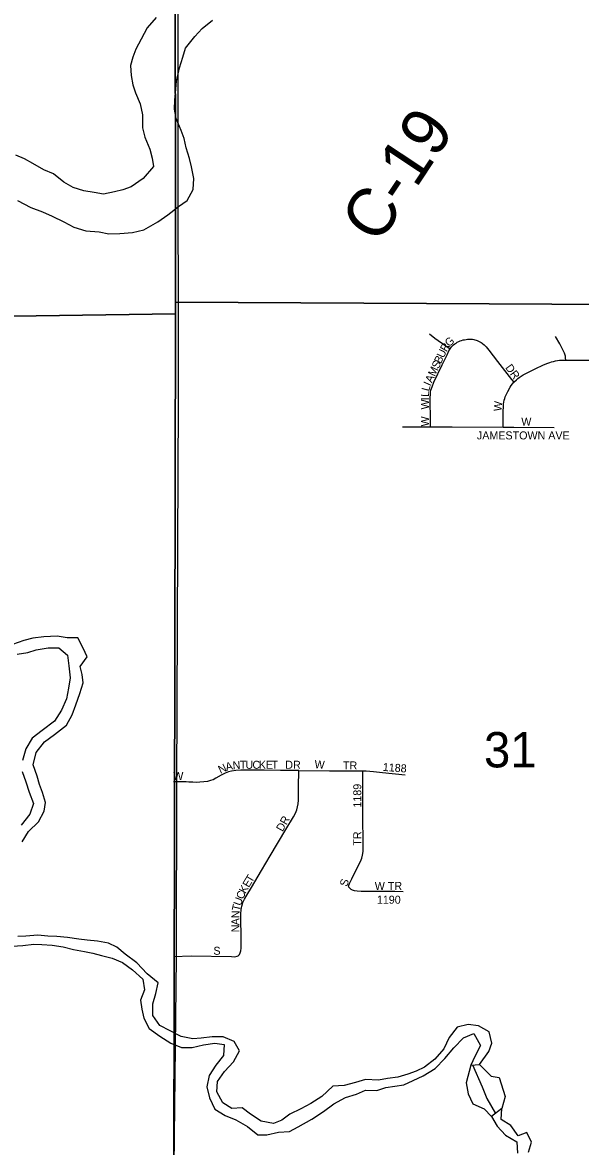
# Model space of a CAD drawing. Extents: x 1772825 to 1773716, y 1138558 to 1139032.
# Drawn here: x 1772827.893 to 1772828.223, y 1138561.147 to 1138561.812 of the extents above; entities that cross this region are included whole.
import ezdxf

# ---------------------------------------------------------------- set-up
doc = ezdxf.new("R2010")
doc.units = 0
for name, color, linetype in [('GM_X_County_Road_Text', 7, 'Continuous'), ('GM_X_Major_River', 7, 'Continuous'), ('GM_X_Minor_Lake', 7, 'Continuous'), ('GM_X_Minor_River', 7, 'Continuous'), ('GM_X_Section', 7, 'Continuous'), ('GM_X_Section_Text', 7, 'Continuous'), ('GM_X_Township', 7, 'Continuous'), ('GM_X_Township_Subdivision', 7, 'Continuous'), ('GM_X_Township_Subdivision_Text', 7, 'Continuous')]:
    doc.layers.add(name, color=color, linetype=linetype)

msp = doc.modelspace()

# ---------------------------------------------------------------- linework, layer by layer
at = {"layer": 'GM_X_Major_River'}
for points in [[(1772827.88993, 1138561.70647), (1772827.89787, 1138561.70243), (1772827.90468, 1138561.69972), (1772827.91055, 1138561.69721), (1772827.91735, 1138561.69393), (1772827.92321, 1138561.69066), (1772827.9304, 1138561.68852), (1772827.93818, 1138561.68789), (1772827.94405, 1138561.68671), (1772827.9505, 1138561.68704), (1772827.95791, 1138561.68755), (1772827.96475, 1138561.68921), (1772827.97294, 1138561.69389), (1772827.97885, 1138561.69802), (1772827.98515, 1138561.7029), (1772827.9903, 1138561.70647), (1772827.99395, 1138561.71308), (1772827.99419, 1138561.71953), (1772827.99291, 1138561.72637), (1772827.99162, 1138561.73131), (1772827.98977, 1138561.73759), (1772827.98848, 1138561.7431), (1772827.98681, 1138561.74786), (1772827.98382, 1138561.7549), (1772827.98291, 1138561.76041), (1772827.98295, 1138561.76591), (1772827.98357, 1138561.77236), (1772827.98398, 1138561.7771), (1772827.98575, 1138561.78487), (1772827.98769, 1138561.7913), (1772827.98925, 1138561.7966), (1772827.9948, 1138561.80339), (1772827.9992, 1138561.80829), (1772828.00531, 1138561.81318)], [(1772827.97192, 1138561.81476), (1772827.96657, 1138561.80854), (1772827.9631, 1138561.80193), (1772827.96002, 1138561.79607), (1772827.95809, 1138561.79115), (1772827.95673, 1138561.78623), (1772827.95725, 1138561.78034), (1772827.95816, 1138561.77483), (1772827.95984, 1138561.77007), (1772827.96245, 1138561.7636), (1772827.96392, 1138561.75714), (1772827.96386, 1138561.74936), (1772827.96534, 1138561.74385), (1772827.96832, 1138561.7368), (1772827.96961, 1138561.73148), (1772827.97033, 1138561.72654)], [(1772827.97033, 1138561.72654), (1772827.96421, 1138561.71957), (1772827.95716, 1138561.7145), (1772827.95221, 1138561.71283), (1772827.94727, 1138561.71154), (1772827.94081, 1138561.71026), (1772827.93531, 1138561.71125), (1772827.92925, 1138561.71225), (1772827.92281, 1138561.71419), (1772827.91733, 1138561.71727), (1772827.9113, 1138561.72225), (1772827.90562, 1138561.72457), (1772827.89901, 1138561.72842), (1772827.8941, 1138561.73111), (1772827.88899, 1138561.73324)], [(1772827.89267, 1138561.32717), (1772827.89651, 1138561.3334), (1772827.90244, 1138561.33905), (1772827.90571, 1138561.34529), (1772827.9065, 1138561.3504), (1772827.90484, 1138561.3563), (1772827.90298, 1138561.36106), (1772827.90168, 1138561.366), (1772827.89927, 1138561.37266), (1772827.90103, 1138561.38004), (1772827.906, 1138561.38627), (1772827.91192, 1138561.39078), (1772827.91898, 1138561.39622), (1772827.92225, 1138561.40227), (1772827.92438, 1138561.40833), (1772827.9269, 1138561.41495), (1772827.92884, 1138561.42119), (1772827.92811, 1138561.42613), (1772827.92701, 1138561.43088), (1772827.93123, 1138561.43654), (1772827.9288, 1138561.44169), (1772827.92562, 1138561.44778), (1772827.91936, 1138561.44783), (1772827.91348, 1138561.44882), (1772827.90551, 1138561.4485), (1772827.89905, 1138561.4476), (1772827.89373, 1138561.44631), (1772827.88707, 1138561.4439)], [(1772827.88969, 1138561.43819), (1772827.89615, 1138561.43928), (1772827.90109, 1138561.44076), (1772827.90812, 1138561.44203), (1772827.91438, 1138561.44198), (1772827.91947, 1138561.43758), (1772827.92037, 1138561.43131), (1772827.92108, 1138561.42429), (1772827.92009, 1138561.41803), (1772827.9189, 1138561.41178), (1772827.91601, 1138561.40516), (1772827.91179, 1138561.39856), (1772827.90454, 1138561.39311), (1772827.89862, 1138561.3886), (1772827.89497, 1138561.38218), (1772827.89283, 1138561.37536)], [(1772827.89279, 1138561.36891), (1772827.89483, 1138561.36264), (1772827.89687, 1138561.35655), (1772827.89948, 1138561.34989), (1772827.89716, 1138561.34364), (1772827.89218, 1138561.33704)], [(1772827.88672, 1138561.26556), (1772827.89317, 1138561.26589), (1772827.89963, 1138561.26679), (1772827.90437, 1138561.26656), (1772827.91044, 1138561.26613), (1772827.91688, 1138561.26514), (1772827.92313, 1138561.26357), (1772827.92958, 1138561.26238), (1772827.9345, 1138561.2614), (1772827.93961, 1138561.26003), (1772827.94586, 1138561.25847), (1772827.95211, 1138561.25595), (1772827.95796, 1138561.25154), (1772827.96399, 1138561.246), (1772827.96508, 1138561.23973), (1772827.96276, 1138561.23367), (1772827.96348, 1138561.22836), (1772827.96458, 1138561.22304), (1772827.96776, 1138561.21675), (1772827.97418, 1138561.21234), (1772827.9806, 1138561.20812), (1772827.98703, 1138561.2056), (1772827.99329, 1138561.20555), (1772827.99994, 1138561.20721), (1772828.00659, 1138561.20811), (1772828.01227, 1138561.20731), (1772828.01185, 1138561.20086), (1772828.00725, 1138561.1952), (1772828.00322, 1138561.18897), (1772828.00185, 1138561.18234), (1772828.00351, 1138561.17588), (1772828.00668, 1138561.16922), (1772828.01273, 1138561.16538), (1772828.01916, 1138561.16286), (1772828.02596, 1138561.15882), (1772828.03219, 1138561.15403), (1772828.0375, 1138561.15399), (1772828.04434, 1138561.15546), (1772828.05079, 1138561.15598), (1772828.05594, 1138561.1586), (1772828.06394, 1138561.16328), (1772828.07099, 1138561.16778)], [(1772828.02282, 1138561.16985), (1772828.01674, 1138561.16952), (1772828.01145, 1138561.17278), (1772828.0079, 1138561.17945), (1772828.00832, 1138561.18552), (1772828.01235, 1138561.19137), (1772828.0177, 1138561.19721), (1772828.02117, 1138561.20363), (1772828.01817, 1138561.20916), (1772828.01155, 1138561.21187), (1772828.0051, 1138561.21191), (1772827.99864, 1138561.2112), (1772827.99371, 1138561.21067), (1772827.9867, 1138561.21205), (1772827.98027, 1138561.21552), (1772827.97422, 1138561.2186), (1772827.97009, 1138561.22451), (1772827.96995, 1138561.23134), (1772827.9717, 1138561.23759), (1772827.97308, 1138561.24384), (1772827.96667, 1138561.2492), (1772827.96045, 1138561.2557), (1772827.95366, 1138561.26087), (1772827.94876, 1138561.2649), (1772827.94384, 1138561.26721), (1772827.93721, 1138561.2684), (1772827.93114, 1138561.26901), (1772827.92621, 1138561.26962), (1772827.91958, 1138561.27062), (1772827.91313, 1138561.27124), (1772827.90782, 1138561.27147), (1772827.90195, 1138561.27208), (1772827.89492, 1138561.27138), (1772827.89018, 1138561.27122)], [(1772828.16322, 1138561.19554), (1772828.16877, 1138561.20327), (1772828.17052, 1138561.20819), (1772828.16886, 1138561.21484), (1772828.16262, 1138561.2185), (1772828.15656, 1138561.21911), (1772828.14991, 1138561.21765), (1772828.14531, 1138561.21142), (1772828.14203, 1138561.2048), (1772828.13687, 1138561.19877), (1772828.13057, 1138561.19389), (1772828.12581, 1138561.19165), (1772828.12086, 1138561.18979), (1772828.11497, 1138561.18812), (1772828.1087, 1138561.18722), (1772828.10338, 1138561.18631), (1772828.0958, 1138561.18675), (1772828.0899, 1138561.1849), (1772828.08325, 1138561.18305), (1772828.07641, 1138561.18273), (1772828.06992, 1138561.1767), (1772828.06344, 1138561.17239), (1772828.05753, 1138561.1694), (1772828.05106, 1138561.16622), (1772828.04629, 1138561.16265), (1772828.04134, 1138561.1606), (1772828.03414, 1138561.16199), (1772828.02772, 1138561.16621), (1772828.02282, 1138561.16985)], [(1772828.07099, 1138561.16778), (1772828.0771, 1138561.17229), (1772828.08395, 1138561.17603), (1772828.09042, 1138561.17807), (1772828.09575, 1138561.1803), (1772828.10239, 1138561.18025), (1772828.10771, 1138561.18192), (1772828.11322, 1138561.18264), (1772828.11854, 1138561.18354), (1772828.12387, 1138561.18616), (1772828.12996, 1138561.18877), (1772828.13702, 1138561.19327), (1772828.14275, 1138561.19911), (1772828.14811, 1138561.20533), (1772828.15365, 1138561.21136), (1772828.15993, 1138561.21396), (1772828.16387, 1138561.20672), (1772828.1604, 1138561.2003), (1772828.15809, 1138561.1952), (1772828.16322, 1138561.19554)], [(1772828.16322, 1138561.19554), (1772828.17018, 1138561.18865), (1772828.17492, 1138561.18786), (1772828.17842, 1138561.17655), (1772828.17649, 1138561.16944)], [(1772828.17649, 1138561.16944), (1772828.1702, 1138561.16475), (1772828.17357, 1138561.15903), (1772828.17866, 1138561.15368), (1772828.18527, 1138561.14984), (1772828.1856, 1138561.14319)], [(1772828.19224, 1138561.14371), (1772828.19399, 1138561.14958), (1772828.19119, 1138561.15529), (1772828.18605, 1138561.15344), (1772828.18173, 1138561.15954), (1772828.17607, 1138561.163), (1772828.17649, 1138561.16944)]]:
    msp.add_lwpolyline(points, dxfattribs=at)
at = {"layer": 'GM_X_Minor_Lake'}
msp.add_lwpolyline([(1772828.16322, 1138561.19554), (1772828.17018, 1138561.18865), (1772828.17492, 1138561.18786), (1772828.17842, 1138561.17655), (1772828.17649, 1138561.16944)], dxfattribs=at)
at = {"layer": 'GM_X_Minor_River'}
for points in [[(1772828.15809, 1138561.1952), (1772828.15536, 1138561.18478), (1772828.15645, 1138561.17813), (1772828.15925, 1138561.17223), (1772828.16587, 1138561.16934), (1772828.1702, 1138561.16475)], [(1772828.15899, 1138561.19526), (1772828.16482, 1138561.18224), (1772828.16762, 1138561.17539), (1772828.17266, 1138561.16659)]]:
    msp.add_lwpolyline(points, dxfattribs=at)
at = {"layer": 'GM_X_Section'}
for points in [[(1772827.98305, 1138562.13959), (1772827.9835, 1138561.6464), (1772827.98344, 1138561.63939), (1772827.47523, 1138561.63224), (1772827.47601, 1138562.13755), (1772827.98288, 1138562.14225)], [(1772828.50962, 1138562.14244), (1772828.50281, 1138561.64361), (1772827.9835, 1138561.6464), (1772827.98305, 1138562.13959)], [(1772827.9835, 1138561.6464), (1772828.50281, 1138561.64361), (1772828.49728, 1138561.13776), (1772827.98248, 1138561.13655), (1772827.98344, 1138561.63939)], [(1772827.47523, 1138561.63224), (1772827.98344, 1138561.63939), (1772827.98248, 1138561.13655), (1772827.4796, 1138561.13163)]]:
    msp.add_lwpolyline(points, close=True, dxfattribs=at)
at = {"layer": 'GM_X_Township'}
msp.add_lwpolyline([(1772827.98261, 1138561.13548), (1772827.98394, 1138561.25873), (1772827.98427, 1138561.36187), (1772827.98501, 1138561.54767), (1772827.98515, 1138561.58446), (1772827.98484, 1138561.94457), (1772827.9869, 1138562.12272), (1772827.98722, 1138562.15071), (1772827.98827, 1138562.24218), (1772827.98864, 1138562.27418), (1772827.98933, 1138562.33404), (1772827.98964, 1138562.36101), (1772827.99004, 1138562.39547), (1772827.99032, 1138562.41938), (1772827.99101, 1138562.47977), (1772827.99121, 1138562.49706), (1772827.99202, 1138562.56761), (1772827.99474, 1138562.80357), (1772827.99538, 1138562.85839), (1772827.99664, 1138562.96764), (1772828.00131, 1138563.14603), (1772828.01473, 1138563.64552)], dxfattribs=at)
msp.add_lwpolyline([(1772827.98261, 1138561.13548), (1772827.98394, 1138561.25873), (1772827.98427, 1138561.36187), (1772827.98501, 1138561.54767), (1772827.98515, 1138561.58446), (1772827.98484, 1138561.94457), (1772827.9869, 1138562.12272), (1772827.98722, 1138562.15071), (1772827.98827, 1138562.24218), (1772827.98864, 1138562.27418), (1772827.98933, 1138562.33404), (1772827.98964, 1138562.36101), (1772827.99004, 1138562.39547), (1772827.99032, 1138562.41938), (1772827.99101, 1138562.47977), (1772827.99121, 1138562.49706), (1772827.99202, 1138562.56761), (1772827.99474, 1138562.80357), (1772827.99538, 1138562.85839), (1772827.99664, 1138562.96764), (1772828.00131, 1138563.14603), (1772828.01473, 1138563.64552)], dxfattribs=at)
at = {"layer": 'GM_X_Township_Subdivision'}
for points in [[(1772828.13357, 1138561.62768), (1772828.13686, 1138561.62514), (1772828.14332, 1138561.62051), (1772828.14581, 1138561.61873)], [(1772828.14581, 1138561.61873), (1772828.14664, 1138561.61994), (1772828.14724, 1138561.6206), (1772828.14789, 1138561.62115), (1772828.14859, 1138561.62169), (1772828.14937, 1138561.6222), (1772828.15004, 1138561.62261), (1772828.15091, 1138561.62304), (1772828.15181, 1138561.62344), (1772828.15256, 1138561.6237), (1772828.15358, 1138561.62401), (1772828.15432, 1138561.62418), (1772828.15527, 1138561.62436), (1772828.15611, 1138561.62445), (1772828.15687, 1138561.62451), (1772828.15768, 1138561.62449), (1772828.15838, 1138561.62445), (1772828.1591, 1138561.62438), (1772828.15981, 1138561.62428), (1772828.1605, 1138561.62412), (1772828.16123, 1138561.62389), (1772828.1619, 1138561.62363), (1772828.16262, 1138561.62331), (1772828.16337, 1138561.62293), (1772828.16427, 1138561.62241), (1772828.16483, 1138561.62202), (1772828.16526, 1138561.62169), (1772828.16591, 1138561.62118), (1772828.16652, 1138561.62062), (1772828.16717, 1138561.61992), (1772828.16867, 1138561.61805), (1772828.17381, 1138561.61135), (1772828.18212, 1138561.60067), (1772828.18344, 1138561.59896)], [(1772828.21417, 1138561.61214), (1772828.21409, 1138561.61351), (1772828.21399, 1138561.61438), (1772828.21386, 1138561.61508), (1772828.21349, 1138561.61627), (1772828.21275, 1138561.61783), (1772828.21073, 1138561.62162), (1772828.20823, 1138561.62605)], [(1772828.13422, 1138561.57264), (1772828.1342, 1138561.5752), (1772828.13411, 1138561.59025), (1772828.13414, 1138561.59157), (1772828.13422, 1138561.59267), (1772828.1343, 1138561.59341), (1772828.1345, 1138561.5944), (1772828.13475, 1138561.59535), (1772828.13512, 1138561.59637), (1772828.13625, 1138561.59897), (1772828.14114, 1138561.60921), (1772828.14398, 1138561.61526), (1772828.14509, 1138561.61749), (1772828.14581, 1138561.61873)], [(1772828.18344, 1138561.59896), (1772828.18505, 1138561.60052), (1772828.18584, 1138561.60118), (1772828.18664, 1138561.60177), (1772828.18779, 1138561.60255), (1772828.18902, 1138561.60329), (1772828.19642, 1138561.60711), (1772828.20069, 1138561.60915), (1772828.20206, 1138561.60975), (1772828.20353, 1138561.61032), (1772828.20473, 1138561.61073), (1772828.20586, 1138561.61107), (1772828.20695, 1138561.61135), (1772828.20824, 1138561.61163), (1772828.20942, 1138561.61185), (1772828.21057, 1138561.61201), (1772828.21176, 1138561.61209), (1772828.21311, 1138561.61214), (1772828.21417, 1138561.61214)], [(1772828.21417, 1138561.61214), (1772828.22489, 1138561.61213), (1772828.23949, 1138561.61201), (1772828.24552, 1138561.61199)], [(1772828.17714, 1138561.57244), (1772828.17717, 1138561.57455), (1772828.17725, 1138561.5817), (1772828.17733, 1138561.58465), (1772828.17743, 1138561.58618), (1772828.1776, 1138561.58725), (1772828.17784, 1138561.5884), (1772828.17815, 1138561.58946), (1772828.17842, 1138561.59029), (1772828.17882, 1138561.59126), (1772828.17987, 1138561.59348), (1772828.18135, 1138561.59616), (1772828.18202, 1138561.59715), (1772828.18267, 1138561.59801), (1772828.18344, 1138561.59896)], [(1772828.11767, 1138561.57273), (1772828.13422, 1138561.57264)], [(1772828.13422, 1138561.57264), (1772828.14711, 1138561.57257), (1772828.17714, 1138561.57244)], [(1772828.17714, 1138561.57244), (1772828.18346, 1138561.57241), (1772828.20739, 1138561.57226)], [(1772828.05629, 1138561.36939), (1772828.05228, 1138561.36944), (1772828.04544, 1138561.36943), (1772828.0358, 1138561.36954), (1772828.02212, 1138561.36959), (1772828.01901, 1138561.3694), (1772828.01656, 1138561.36902), (1772828.01476, 1138561.36855), (1772828.01272, 1138561.36779), (1772828.01048, 1138561.36671), (1772828.00723, 1138561.36486), (1772828.0056, 1138561.36398), (1772828.00416, 1138561.36341), (1772828.00237, 1138561.36296), (1772828.00024, 1138561.36264), (1772827.99778, 1138561.36244), (1772827.99561, 1138561.3624), (1772827.99375, 1138561.36246), (1772827.99126, 1138561.36256), (1772827.98971, 1138561.36263), (1772827.98457, 1138561.36273), (1772827.98219, 1138561.36278)], [(1772827.98231, 1138561.25946), (1772827.99261, 1138561.25973), (1772828.01654, 1138561.25933), (1772828.01801, 1138561.25926), (1772828.01903, 1138561.25936), (1772828.01993, 1138561.25953), (1772828.02043, 1138561.25979), (1772828.02119, 1138561.26066), (1772828.02162, 1138561.26151), (1772828.02203, 1138561.26279), (1772828.02221, 1138561.26429), (1772828.02233, 1138561.26574), (1772828.02218, 1138561.27226), (1772828.02195, 1138561.28063), (1772828.02198, 1138561.28435), (1772828.02222, 1138561.28714), (1772828.02264, 1138561.28926), (1772828.02331, 1138561.29133), (1772828.02423, 1138561.2933), (1772828.02556, 1138561.29576), (1772828.02826, 1138561.3003), (1772828.03418, 1138561.31017), (1772828.03935, 1138561.31902), (1772828.04866, 1138561.33445), (1772828.05315, 1138561.34191), (1772828.05431, 1138561.34411), (1772828.05513, 1138561.34612), (1772828.05563, 1138561.34791), (1772828.05594, 1138561.34974), (1772828.05611, 1138561.35191), (1772828.05623, 1138561.35968), (1772828.05629, 1138561.36939)], [(1772828.05629, 1138561.36939), (1772828.07442, 1138561.36925), (1772828.08891, 1138561.36922), (1772828.09428, 1138561.36914)], [(1772828.08624, 1138561.30002), (1772828.08601, 1138561.30032), (1772828.08585, 1138561.3006), (1772828.08573, 1138561.30106), (1772828.08585, 1138561.30161), (1772828.08634, 1138561.30258), (1772828.08775, 1138561.30533), (1772828.09013, 1138561.31031), (1772828.09277, 1138561.31562), (1772828.09362, 1138561.31762), (1772828.09409, 1138561.31941), (1772828.0943, 1138561.32158), (1772828.09436, 1138561.33061), (1772828.09429, 1138561.33808), (1772828.09421, 1138561.35489), (1772828.09427, 1138561.3661), (1772828.09428, 1138561.36914)], [(1772828.09428, 1138561.36914), (1772828.0961, 1138561.36911), (1772828.10046, 1138561.36885), (1772828.10574, 1138561.36827), (1772828.11921, 1138561.36692)], [(1772828.08624, 1138561.30002), (1772828.0867, 1138561.29955), (1772828.08717, 1138561.2992), (1772828.08791, 1138561.29882), (1772828.08911, 1138561.29847), (1772828.09081, 1138561.2982), (1772828.09323, 1138561.29799), (1772828.09726, 1138561.29799), (1772828.10409, 1138561.29802), (1772828.11309, 1138561.29805), (1772828.11806, 1138561.29792)]]:
    msp.add_lwpolyline(points, dxfattribs=at)

# ---------------------------------------------------------------- texts
at = {"layer": 'GM_X_County_Road_Text'}
msp.add_text('C-19', height=0.028409, rotation=56.40386, dxfattribs=at).set_placement((1772828.10339, 1138561.6798))
at = {"layer": 'GM_X_Section_Text'}
msp.add_text('31', height=0.020928, rotation=0.00001, dxfattribs=at).set_placement((1772828.16583, 1138561.37123))
at = {"layer": 'GM_X_Township_Subdivision_Text'}
for s, height, rotation, p in [('G', 0.00473, 42.82056, (1772828.14528, 1138561.61964)), ('U', 0.00473, 64.62917, (1772828.14194, 1138561.61298)), ('R', 0.00473, 60.7732, (1772828.14369, 1138561.61667)), ('S', 0.00473, 64.64272, (1772828.13891, 1138561.60658)), ('B', 0.00473, 64.62956, (1772828.14033, 1138561.60959)), ('M', 0.00473, 64.62436, (1772828.13676, 1138561.60206)), ('DR', 0.004735, 306.24942, (1772828.17822, 1138561.60756)), ('I', 0.00473, 65.5271, (1772828.13414, 1138561.59641)), ('A', 0.00473, 64.90124, (1772828.135, 1138561.59829)), ('L', 0.00473, 88.36029, (1772828.13331, 1138561.59034)), ('L', 0.00473, 75.19526, (1772828.13336, 1138561.59338)), ('W', 0.00473, 89.76463, (1772828.13328, 1138561.58287)), ('I', 0.00473, 89.75564, (1772828.1333, 1138561.58828)), ('W', 0.00473, 85.58714, (1772828.1762, 1138561.58169)), ('W', 0.00473, 90, (1772828.13328, 1138561.57287)), ('W', 0.00473, 0.00001, (1772828.18792, 1138561.57334)), ('JAMESTOWN AVE', 0.0047348, 0.00001, (1772828.16167, 1138561.5652)), ('N', 0.00473, 25.07896, (1772828.00999, 1138561.36741)), ('A', 0.00473, 14.24297, (1772828.01354, 1138561.36909)), ('N', 0.00473, 4.33165, (1772828.01736, 1138561.37008)), ('T', 0.00473, 0.6284, (1772828.02144, 1138561.37039)), ('U', 0.00473, 0.00001, (1772828.02476, 1138561.37043)), ('C', 0.00473, 0.00001, (1772828.02892, 1138561.37043)), ('K', 0.00473, 0.00001, (1772828.03267, 1138561.37043)), ('E', 0.00473, 0.00001, (1772828.03684, 1138561.37043)), ('T', 0.00473, 0.00001, (1772828.04017, 1138561.37043)), ('DR', 0.004735, 0.00001, (1772828.04833, 1138561.37043)), ('W', 0.00473, 355.58715, (1772828.06549, 1138561.37084)), ('TR', 0.004735, 0.00001, (1772828.0825, 1138561.37001)), ('1188', 0.004735, 356.05688, (1772828.1059, 1138561.36918)), ('W', 0.00473, 0.00001, (1772827.98208, 1138561.36376)), ('1189', 0.004735, 90, (1772828.09328, 1138561.34746)), ('DR', 0.004735, 60.64354, (1772828.04672, 1138561.33289)), ('TR', 0.004735, 90, (1772828.09328, 1138561.32496)), ('E', 0.00473, 59.26577, (1772828.02677, 1138561.29982)), ('T', 0.00473, 59.26577, (1772828.02848, 1138561.30268)), ('K', 0.00473, 60.82439, (1772828.02476, 1138561.29621)), ('S', 0.00473, 73.08612, (1772828.08489, 1138561.30043)), ('W TR', 0.004735, 0.00001, (1772828.10125, 1138561.29876)), ('U', 0.00473, 69.4772, (1772828.02192, 1138561.28902)), ('C', 0.00473, 67.1522, (1772828.02336, 1138561.29288)), ('1190', 0.004735, 0.00001, (1772828.1025, 1138561.29063)), ('N', 0.00473, 89.03823, (1772828.02122, 1138561.28202)), ('T', 0.00473, 77.72013, (1772828.02126, 1138561.28594)), ('A', 0.00473, 89.78139, (1772828.02121, 1138561.27787)), ('N', 0.00473, 89.80325, (1772828.02119, 1138561.2737)), ('S', 0.00473, 0.00001, (1772828.00583, 1138561.26043))]:
    msp.add_text(s, height=height, rotation=rotation, dxfattribs=at).set_placement(p)

doc.saveas('drawing.dxf')
